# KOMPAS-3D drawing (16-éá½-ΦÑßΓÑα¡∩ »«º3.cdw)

Views: Вид 1, Вид 2
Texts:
  вАЛ-ШЕСТЕРНЯ
  Noncommercial version
  Заголовки
  Normal
  Ra2.5
  Ra3.2
  Ra3,2
  R 0,3 max
  Ra0.8
  Модуль
  Число зубьев
  Угол наклона
  Symbol type B
  Symbol type A
  Направление линии зуба
  правое
  Нормальный исходный контур
  ГОСТ 13755-81
  Коэффициент смещения
  Средняя длина общей нормали
  Делительный диаметр
  Высота зуба
  Обозначение чертежа сопряженного зубчатого колеса
  Ra12,5
  1. Улучшение; 235...262 HВ.
  2.  H14, h14,    IT14 2 .
  3. * Размер обеспечить инструментом.
  Сталь 45Х ГОСТ 4543-71
  ТФ ДГТУ
Dimensions and other numbers on the sheet: 230; 28; 30; 25; 82; 8; 70; 45; 77,53; 1,6; 47,5; 48; 73; 400; 3 фаски; 1; 6; 12; 22; 0,02; 0,004; 0,025; 3,5; 20; 0; 26,833 -0,060 -0,160; 70,53; 7,88; 000.09; 0,05; 0,04; 0,086; 3; 0,3; 0,5; 1:1; 2; 0,98; 4; 5; 7; 9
